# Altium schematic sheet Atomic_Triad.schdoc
size 594 x 419 mm; Symbol: Drawing-Symbol_A4; @Project Name: Inverted_MAML_6x6; @Page Count: 1; @Update Date: 2026-06-10; @Create Date: 2026-06-10; @Schematic Name: Schematic1; @Page No: 1; @Page Name: P1; Company: EasyEDA.com; Version: V1.0; Page Size: A4; Drawn: Olle Welin; Device: Drawing-Symbol_A4; @Create Time: 18:31:32; @Update Time: 18:31:32; Border: 1; Width: 2338; Height: 1652; Region Start: 1; X Region Count: 6; Y Region Count: 4; Blade Width: 10; Title Block Position: 3; @Board Name: Analog_Matrix
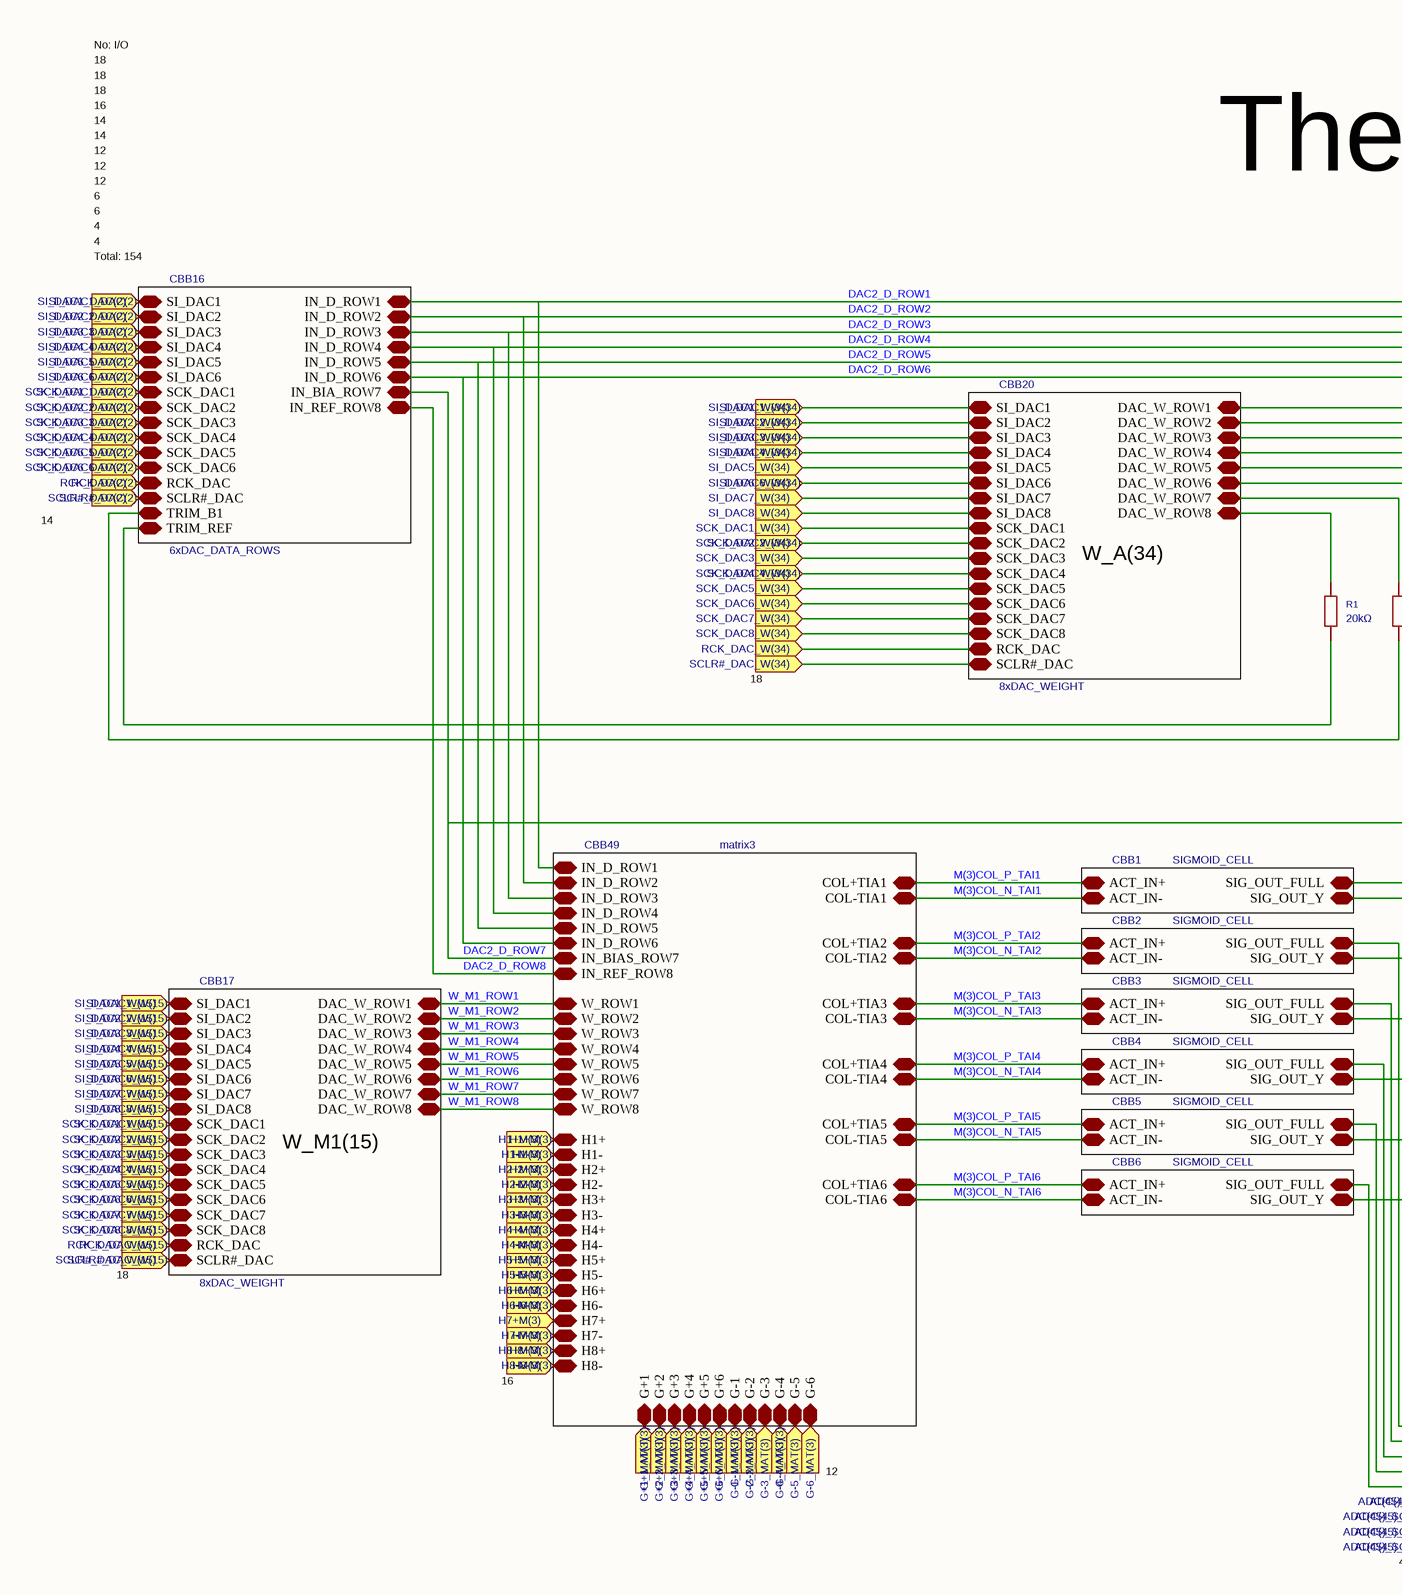
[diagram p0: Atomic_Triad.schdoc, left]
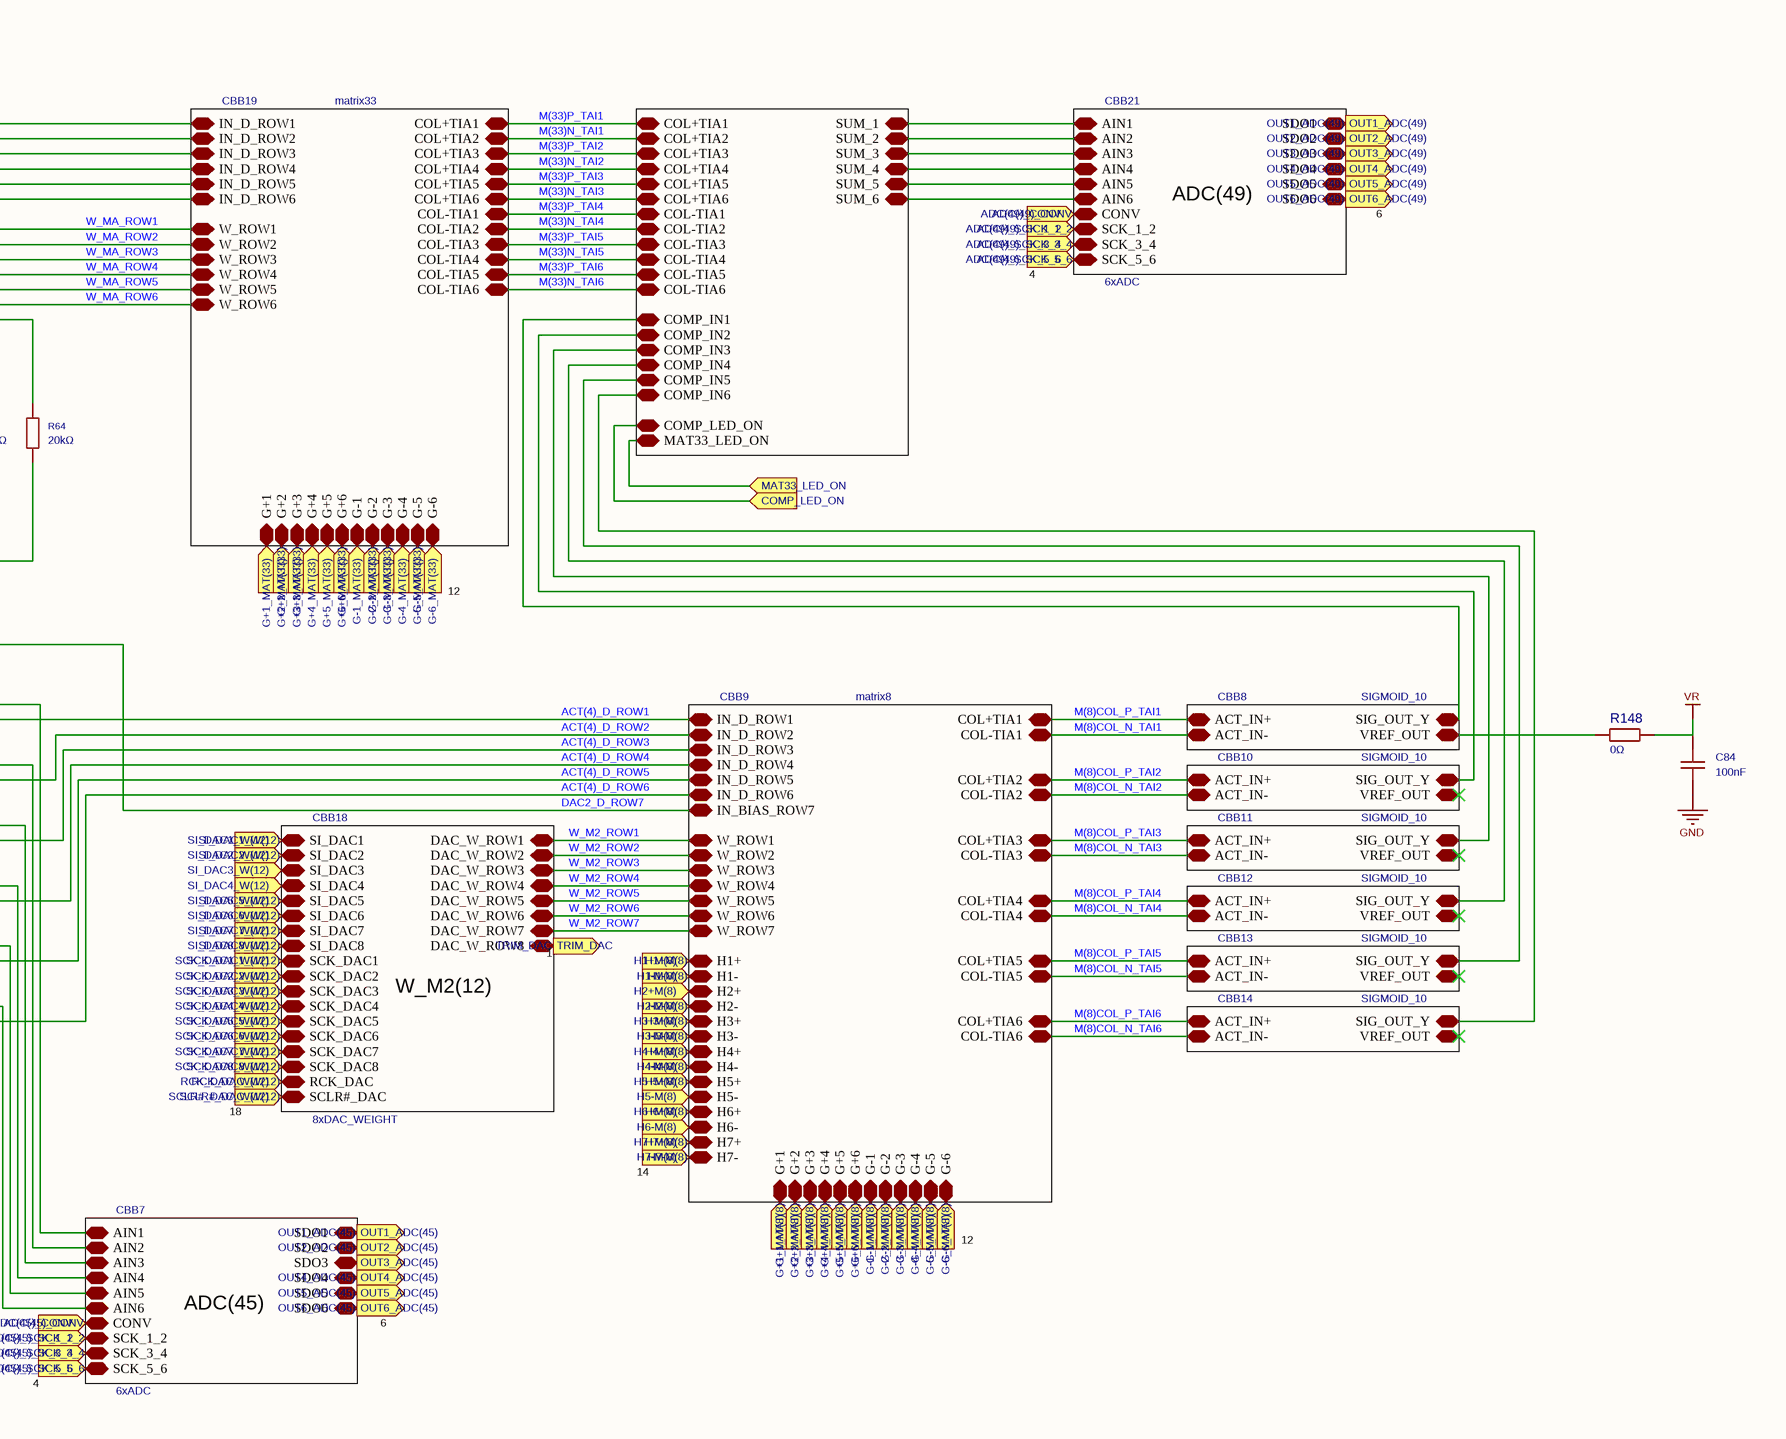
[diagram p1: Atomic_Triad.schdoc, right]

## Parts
C84  100nF  [C0402]
R1  20kΩ  [R0402]
R64  20kΩ  [R0402]
R148  0Ω  [R0402]

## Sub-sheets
CBB1 = SIMOID(4).schdoc: ACT_IN-, ACT_IN+, SIG_OUT_FULL, SIG_OUT_Y  | Symbol: SIGMOID_CELL
CBB2 = SIMOID(4).schdoc: ACT_IN-, ACT_IN+, SIG_OUT_FULL, SIG_OUT_Y  | Symbol: SIGMOID_CELL
CBB3 = SIMOID(4).schdoc: ACT_IN-, ACT_IN+, SIG_OUT_FULL, SIG_OUT_Y  | Symbol: SIGMOID_CELL
CBB4 = SIMOID(4).schdoc: ACT_IN-, ACT_IN+, SIG_OUT_FULL, SIG_OUT_Y  | Symbol: SIGMOID_CELL
CBB5 = SIMOID(4).schdoc: ACT_IN-, ACT_IN+, SIG_OUT_FULL, SIG_OUT_Y  | Symbol: SIGMOID_CELL
CBB6 = SIMOID(4).schdoc: ACT_IN-, ACT_IN+, SIG_OUT_FULL, SIG_OUT_Y  | Symbol: SIGMOID_CELL
CBB7 = ADC_BANK.schdoc: AIN1, CONV, SCK_1_2, SDO1, SDO2, SDO3, SDO4, SDO5, SDO6, AIN2, AIN3, AIN4, AIN5, AIN6, SCK_3_4, SCK_5_6  | Symbol: 6xADC
CBB8 = SIGMOID(10).schdoc: ACT_IN-, ACT_IN+, SIG_OUT_Y, VREF_OUT  | Symbol: SIGMOID_10
CBB9 = matx8.schdoc: H7+, H7-, H6-, H5-, H4-, H3-, H2-, H1-, H6+, H5+, H4+, H3+, H2+, H1+, COL-TIA6, COL-TIA5, COL-TIA4, COL-TIA3, COL-TIA2, COL-TIA1, COL+TIA6, COL+TIA5, COL+TIA4, COL+TIA3, COL+TIA2, COL+TIA1, G-6, G-5, G-4, G-3, G-2, G-1, G+6, G+5, G+4, G+3, G+2, G+1, IN_D_ROW1, IN_D_ROW2, IN_D_ROW3, IN_D_ROW4, IN_D_ROW5, IN_D_ROW6, W_ROW1, W_ROW2, W_ROW3, W_ROW4, W_ROW5, W_ROW6, W_ROW7, IN_BIAS_ROW7  | Symbol: matrix8
CBB10 = SIGMOID(10).schdoc: ACT_IN-, ACT_IN+, SIG_OUT_Y, VREF_OUT  | Symbol: SIGMOID_10
CBB11 = SIGMOID(10).schdoc: ACT_IN-, ACT_IN+, SIG_OUT_Y, VREF_OUT  | Symbol: SIGMOID_10
CBB12 = SIGMOID(10).schdoc: ACT_IN-, ACT_IN+, SIG_OUT_Y, VREF_OUT  | Symbol: SIGMOID_10
CBB13 = SIGMOID(10).schdoc: ACT_IN-, ACT_IN+, SIG_OUT_Y, VREF_OUT  | Symbol: SIGMOID_10
CBB14 = SIGMOID(10).schdoc: ACT_IN-, ACT_IN+, SIG_OUT_Y, VREF_OUT  | Symbol: SIGMOID_10
CBB15 = sum35.schdoc: COL+TIA1, COL+TIA2, COL+TIA3, COL+TIA4, COL+TIA5, COL+TIA6, COL-TIA1, COL-TIA2, COL-TIA3, COL-TIA4, COL-TIA5, COL-TIA6, COMP_IN1, COMP_IN2, COMP_IN3, COMP_IN4, COMP_IN5, COMP_IN6, SUM_1, SUM_2, SUM_3, SUM_4, SUM_5, SUM_6, COMP_LED_ON, MAT33_LED_ON  | Symbol: SUM35
CBB16 = 6xDAC_8-bit.schdoc: SI_DAC1, SI_DAC2, SI_DAC3, SI_DAC4, SI_DAC5, SI_DAC6, SCK_DAC1, SCK_DAC2, SCK_DAC3, SCK_DAC4, SCK_DAC5, SCK_DAC6, RCK_DAC, SCLR#_DAC, IN_BIA_ROW7, IN_REF_ROW8, IN_D_ROW1, IN_D_ROW2, IN_D_ROW3, IN_D_ROW4, IN_D_ROW5, IN_D_ROW6, TRIM_B1, TRIM_REF  | Symbol: 6xDAC_DATA_ROWS
CBB17 = 8xDAC_WEIGHT_8xDAC_8-bit.schdoc: SI_DAC1, SI_DAC2, SI_DAC3, SI_DAC4, SI_DAC5, SI_DAC6, SI_DAC7, SI_DAC8, SCK_DAC1, SCK_DAC2, SCK_DAC3, SCK_DAC4, SCK_DAC5, SCK_DAC6, SCK_DAC7, SCK_DAC8, RCK_DAC, SCLR#_DAC, DAC_W_ROW1, DAC_W_ROW2, DAC_W_ROW3, DAC_W_ROW4, DAC_W_ROW5, DAC_W_ROW6, DAC_W_ROW7, DAC_W_ROW8  | Symbol: 8xDAC_WEIGHT
CBB18 = 8xDAC_WEIGHT_8xDAC_8-bit.schdoc: SI_DAC1, SI_DAC2, SI_DAC3, SI_DAC4, SI_DAC5, SI_DAC6, SI_DAC7, SI_DAC8, SCK_DAC1, SCK_DAC2, SCK_DAC3, SCK_DAC4, SCK_DAC5, SCK_DAC6, SCK_DAC7, SCK_DAC8, RCK_DAC, SCLR#_DAC, DAC_W_ROW1, DAC_W_ROW2, DAC_W_ROW3, DAC_W_ROW4, DAC_W_ROW5, DAC_W_ROW6, DAC_W_ROW7, DAC_W_ROW8  | Symbol: 8xDAC_WEIGHT
CBB19 = matx33.schdoc: G+1, G+2, G+3, G+4, G+5, G+6, G-1, G-2, G-3, G-4, G-5, G-6, IN_D_ROW1, IN_D_ROW2, IN_D_ROW3, IN_D_ROW4, IN_D_ROW5, IN_D_ROW6, W_ROW1, W_ROW2, W_ROW3, W_ROW4, W_ROW5, W_ROW6, COL+TIA1, COL+TIA2, COL+TIA3, COL+TIA4, COL+TIA5, COL+TIA6, COL-TIA1, COL-TIA2, COL-TIA3, COL-TIA4, COL-TIA5, COL-TIA6  | Symbol: matrix33
CBB20 = 8xDAC_WEIGHT_8xDAC_8-bit.schdoc: SI_DAC1, SI_DAC2, SI_DAC3, SI_DAC4, SI_DAC5, SI_DAC6, SI_DAC7, SI_DAC8, SCK_DAC1, SCK_DAC2, SCK_DAC3, SCK_DAC4, SCK_DAC5, SCK_DAC6, SCK_DAC7, SCK_DAC8, RCK_DAC, SCLR#_DAC, DAC_W_ROW1, DAC_W_ROW2, DAC_W_ROW3, DAC_W_ROW4, DAC_W_ROW5, DAC_W_ROW6, DAC_W_ROW7, DAC_W_ROW8  | Symbol: 8xDAC_WEIGHT
CBB21 = ADC_BANK.schdoc: AIN1, CONV, SCK_1_2, SDO1, SDO2, SDO3, SDO4, SDO5, SDO6, AIN2, AIN3, AIN4, AIN5, AIN6, SCK_3_4, SCK_5_6  | Symbol: 6xADC
CBB49 = matx3.schdoc: G+1, G+2, G+3, G+4, G+5, G+6, G-1, G-2, G-3, G-4, G-5, G-6, COL+TIA1, COL+TIA2, COL+TIA3, COL+TIA4, COL+TIA5, COL+TIA6, COL-TIA1, COL-TIA2, COL-TIA3, COL-TIA4, COL-TIA5, COL-TIA6, H1+, H2+, H3+, H4+, H5+, H6+, H1-, H2-, H3-, H4-, H5-, H6-, H7-, H8-, H7+, H8+, W_ROW1, W_ROW2, W_ROW3, W_ROW4, W_ROW5, W_ROW6, W_ROW7, W_ROW8, IN_D_ROW1, IN_D_ROW2, IN_D_ROW3, IN_D_ROW4, IN_D_ROW5, IN_D_ROW6, IN_BIAS_ROW7, IN_REF_ROW8  | Symbol: matrix3

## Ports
ADC(45)_CONV (in), ADC(45)_SCK_1_2 (in), ADC(45)_SCK_3_4 (in), ADC(45)_SCK_5_6 (in), ADC(49)_CONV (in), ADC(49)_SCK_1_2 (in), ADC(49)_SCK_3_4 (in), ADC(49)_SCK_5_6 (in), COMP_LED_ON (in), G+1_MAT(3) (in), G+1_MAT(8) (in), G+1_MAT(33) (in), G+2_MAT(3) (in), G+2_MAT(8) (in), G+2_MAT(33) (in), G+3_MAT(3) (in), G+3_MAT(8) (in), G+3_MAT(33) (in), G+4_MAT(3) (in), G+4_MAT(8) (in), G+4_MAT(33) (in), G+5_MAT(3) (in), G+5_MAT(8) (in), G+5_MAT(33) (in), G+6_MAT(3) (in), G+6_MAT(8) (in), G+6_MAT(33) (in), G-1_MAT(3) (in), G-1_MAT(8) (in), G-1_MAT(33) (in), G-2_MAT(3) (in), G-2_MAT(8) (in), G-2_MAT(33) (in), G-3_MAT(3) (in), G-3_MAT(8) (in), G-3_MAT(33) (in), G-4_MAT(3) (in), G-4_MAT(8) (in), G-4_MAT(33) (in), G-5_MAT(3) (in), G-5_MAT(8) (in), G-5_MAT(33) (in), G-6_MAT(3) (in), G-6_MAT(8) (in), G-6_MAT(33) (in), H1+M(3) (in), H1+M(8) (in), H1-M(3) (in), H1-M(8) (in), H2+M(3) (in), H2+M(8) (in), H2-M(3) (in), H2-M(8) (in), H3+M(3) (in), H3+M(8) (in), H3-M(3) (in), H3-M(8) (in), H4+M(3) (in), H4+M(8) (in), H4-M(3) (in), H4-M(8) (in), H5+M(3) (in), H5+M(8) (in), H5-M(3) (in), H5-M(8) (in), H6+M(3) (in), H6+M(8) (in), H6-M(3) (in), H6-M(8) (in), H7+M(3) (in), H7+M(8) (in), H7-M(3) (in), H7-M(8) (in), H8+M(3) (in), H8-M(3) (in), MAT33_LED_ON (in), OUT1_ADC(45) (out), OUT1_ADC(49) (out), OUT2_ADC(45) (out), OUT2_ADC(49) (out), OUT3_ADC(45) (out), OUT3_ADC(49) (out), OUT4_ADC(45) (out), OUT4_ADC(49) (out), OUT5_ADC(45) (out), OUT5_ADC(49) (out), OUT6_ADC(45) (out), OUT6_ADC(49) (out), RCK_DAC(2) (in), RCK_DAC_W(12) (in), RCK_DAC_W(15) (in), RCK_DAC_W(34) (in), SCK_DAC1_DAC(2) (in), SCK_DAC1_W(12) (in), SCK_DAC1_W(15) (in), SCK_DAC1_W(34) (in), SCK_DAC2_DAC(2) (in), SCK_DAC2_W(12) (in), SCK_DAC2_W(15) (in), SCK_DAC2_W(34) (in), SCK_DAC3_DAC(2) (in), SCK_DAC3_W(12) (in), SCK_DAC3_W(15) (in), SCK_DAC3_W(34) (in), SCK_DAC4_DAC(2) (in), SCK_DAC4_W(12) (in), SCK_DAC4_W(15) (in), SCK_DAC4_W(34) (in), SCK_DAC5_DAC(2) (in), SCK_DAC5_W(12) (in), SCK_DAC5_W(15) (in), SCK_DAC5_W(34) (in), SCK_DAC6_DAC(2) (in), SCK_DAC6_W(12) (in), SCK_DAC6_W(15) (in), SCK_DAC6_W(34) (in), SCK_DAC7_W(12) (in), SCK_DAC7_W(15) (in), SCK_DAC7_W(34) (in), SCK_DAC8_W(12) (in), SCK_DAC8_W(15) (in), SCK_DAC8_W(34) (in), SCLR#_DAC(2) (in), SCLR#_DAC_W(12) (in), SCLR#_DAC_W(15) (in), SCLR#_DAC_W(34) (in), SI_DAC1_DAC(2) (in), SI_DAC1_W(12) (in), SI_DAC1_W(15) (in), SI_DAC1_W(34) (in), SI_DAC2_DAC(2) (in), SI_DAC2_W(12) (in), SI_DAC2_W(15) (in), SI_DAC2_W(34) (in), SI_DAC3_DAC(2) (in), SI_DAC3_W(12) (in), SI_DAC3_W(15) (in), SI_DAC3_W(34) (in), SI_DAC4_DAC(2) (in), SI_DAC4_W(12) (in), SI_DAC4_W(15) (in), SI_DAC4_W(34) (in), SI_DAC5_DAC(2) (in), SI_DAC5_W(12) (in), SI_DAC5_W(15) (in), SI_DAC5_W(34) (in), SI_DAC6_DAC(2) (in), SI_DAC6_W(12) (in), SI_DAC6_W(15) (in), SI_DAC6_W(34) (in), SI_DAC7_W(12) (in), SI_DAC7_W(15) (in), SI_DAC7_W(34) (in), SI_DAC8_W(12) (in), SI_DAC8_W(15) (in), SI_DAC8_W(34) (in), TRIM_DAC (out)

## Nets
GND: C84.1
VR: C84.2 R148.2
ACT(4)_D_ROW1: sheet CBB1/SIG_OUT_Y, sheet CBB9/IN_D_ROW1
ACT(4)_D_ROW2: sheet CBB2/SIG_OUT_Y, sheet CBB9/IN_D_ROW2
ACT(4)_D_ROW3: sheet CBB3/SIG_OUT_Y, sheet CBB9/IN_D_ROW3
ACT(4)_D_ROW4: sheet CBB4/SIG_OUT_Y, sheet CBB9/IN_D_ROW4
ACT(4)_D_ROW5: sheet CBB5/SIG_OUT_Y, sheet CBB9/IN_D_ROW5
ACT(4)_D_ROW6: sheet CBB6/SIG_OUT_Y, sheet CBB9/IN_D_ROW6
ADC(45)_CONV: port ADC(45)_CONV, sheet CBB7/CONV
ADC(45)_SCK_1_2: port ADC(45)_SCK_1_2, sheet CBB7/SCK_1_2
ADC(45)_SCK_3_4: port ADC(45)_SCK_3_4, sheet CBB7/SCK_3_4
ADC(45)_SCK_5_6: port ADC(45)_SCK_5_6, sheet CBB7/SCK_5_6
ADC(49)_CONV: port ADC(49)_CONV, sheet CBB21/CONV
ADC(49)_SCK_1_2: port ADC(49)_SCK_1_2, sheet CBB21/SCK_1_2
ADC(49)_SCK_3_4: port ADC(49)_SCK_3_4, sheet CBB21/SCK_3_4
ADC(49)_SCK_5_6: port ADC(49)_SCK_5_6, sheet CBB21/SCK_5_6
COMP_LED_ON: port COMP_LED_ON, sheet CBB15/COMP_LED_ON
DAC2_D_ROW1: sheet CBB49/IN_D_ROW1, sheet CBB16/IN_D_ROW1, sheet CBB19/IN_D_ROW1
DAC2_D_ROW2: sheet CBB49/IN_D_ROW2, sheet CBB16/IN_D_ROW2, sheet CBB19/IN_D_ROW2
DAC2_D_ROW3: sheet CBB49/IN_D_ROW3, sheet CBB16/IN_D_ROW3, sheet CBB19/IN_D_ROW3
DAC2_D_ROW4: sheet CBB49/IN_D_ROW4, sheet CBB16/IN_D_ROW4, sheet CBB19/IN_D_ROW4
DAC2_D_ROW5: sheet CBB49/IN_D_ROW5, sheet CBB16/IN_D_ROW5, sheet CBB19/IN_D_ROW5
DAC2_D_ROW6: sheet CBB49/IN_D_ROW6, sheet CBB16/IN_D_ROW6, sheet CBB19/IN_D_ROW6
DAC2_D_ROW7: sheet CBB49/IN_BIAS_ROW7, sheet CBB9/IN_BIAS_ROW7, sheet CBB16/IN_BIA_ROW7
DAC2_D_ROW8: sheet CBB49/IN_REF_ROW8, sheet CBB16/IN_REF_ROW8
G+1_MAT(3): port G+1_MAT(3), sheet CBB49/G+1
G+1_MAT(8): port G+1_MAT(8), sheet CBB9/G+1
G+1_MAT(33): port G+1_MAT(33), sheet CBB19/G+1
G+2_MAT(3): port G+2_MAT(3), sheet CBB49/G+2
G+2_MAT(8): port G+2_MAT(8), sheet CBB9/G+2
G+2_MAT(33): port G+2_MAT(33), sheet CBB19/G+2
G+3_MAT(3): port G+3_MAT(3), sheet CBB49/G+3
G+3_MAT(8): port G+3_MAT(8), sheet CBB9/G+3
G+3_MAT(33): port G+3_MAT(33), sheet CBB19/G+3
G+4_MAT(3): port G+4_MAT(3), sheet CBB49/G+4
G+4_MAT(8): port G+4_MAT(8), sheet CBB9/G+4
G+4_MAT(33): port G+4_MAT(33), sheet CBB19/G+4
G+5_MAT(3): port G+5_MAT(3), sheet CBB49/G+5
G+5_MAT(8): port G+5_MAT(8), sheet CBB9/G+5
G+5_MAT(33): port G+5_MAT(33), sheet CBB19/G+5
G+6_MAT(3): port G+6_MAT(3), sheet CBB49/G+6
G+6_MAT(8): port G+6_MAT(8), sheet CBB9/G+6
G+6_MAT(33): port G+6_MAT(33), sheet CBB19/G+6
G-1_MAT(3): port G-1_MAT(3), sheet CBB49/G-1
G-1_MAT(8): port G-1_MAT(8), sheet CBB9/G-1
G-1_MAT(33): port G-1_MAT(33), sheet CBB19/G-1
G-2_MAT(3): port G-2_MAT(3), sheet CBB49/G-2
G-2_MAT(8): port G-2_MAT(8), sheet CBB9/G-2
G-2_MAT(33): port G-2_MAT(33), sheet CBB19/G-2
G-3_MAT(3): port G-3_MAT(3), sheet CBB49/G-3
G-3_MAT(8): port G-3_MAT(8), sheet CBB9/G-3
G-3_MAT(33): port G-3_MAT(33), sheet CBB19/G-3
G-4_MAT(3): port G-4_MAT(3), sheet CBB49/G-4
G-4_MAT(8): port G-4_MAT(8), sheet CBB9/G-4
G-4_MAT(33): port G-4_MAT(33), sheet CBB19/G-4
G-5_MAT(3): port G-5_MAT(3), sheet CBB49/G-5
G-5_MAT(8): port G-5_MAT(8), sheet CBB9/G-5
G-5_MAT(33): port G-5_MAT(33), sheet CBB19/G-5
G-6_MAT(3): port G-6_MAT(3), sheet CBB49/G-6
G-6_MAT(8): port G-6_MAT(8), sheet CBB9/G-6
G-6_MAT(33): port G-6_MAT(33), sheet CBB19/G-6
H1+M(3): port H1+M(3), sheet CBB49/H1+
H1+M(8): port H1+M(8), sheet CBB9/H1+
H1-M(3): port H1-M(3), sheet CBB49/H1-
H1-M(8): port H1-M(8), sheet CBB9/H1-
H2+M(3): port H2+M(3), sheet CBB49/H2+
H2+M(8): port H2+M(8), sheet CBB9/H2+
H2-M(3): port H2-M(3), sheet CBB49/H2-
H2-M(8): port H2-M(8), sheet CBB9/H2-
H3+M(3): port H3+M(3), sheet CBB49/H3+
H3+M(8): port H3+M(8), sheet CBB9/H3+
H3-M(3): port H3-M(3), sheet CBB49/H3-
H3-M(8): port H3-M(8), sheet CBB9/H3-
H4+M(3): port H4+M(3), sheet CBB49/H4+
H4+M(8): port H4+M(8), sheet CBB9/H4+
H4-M(3): port H4-M(3), sheet CBB49/H4-
H4-M(8): port H4-M(8), sheet CBB9/H4-
H5+M(3): port H5+M(3), sheet CBB49/H5+
H5+M(8): port H5+M(8), sheet CBB9/H5+
H5-M(3): port H5-M(3), sheet CBB49/H5-
H5-M(8): port H5-M(8), sheet CBB9/H5-
H6+M(3): port H6+M(3), sheet CBB49/H6+
H6+M(8): port H6+M(8), sheet CBB9/H6+
H6-M(3): port H6-M(3), sheet CBB49/H6-
H6-M(8): port H6-M(8), sheet CBB9/H6-
H7+M(3): port H7+M(3), sheet CBB49/H7+
H7+M(8): port H7+M(8), sheet CBB9/H7+
H7-M(3): port H7-M(3), sheet CBB49/H7-
H7-M(8): port H7-M(8), sheet CBB9/H7-
H8+M(3): port H8+M(3), sheet CBB49/H8+
H8-M(3): port H8-M(3), sheet CBB49/H8-
M(3)COL_N_TAI1: sheet CBB49/COL-TIA1, sheet CBB1/ACT_IN-
M(3)COL_N_TAI2: sheet CBB49/COL-TIA2, sheet CBB2/ACT_IN-
M(3)COL_N_TAI3: sheet CBB49/COL-TIA3, sheet CBB3/ACT_IN-
M(3)COL_N_TAI4: sheet CBB49/COL-TIA4, sheet CBB4/ACT_IN-
M(3)COL_N_TAI5: sheet CBB49/COL-TIA5, sheet CBB5/ACT_IN-
M(3)COL_N_TAI6: sheet CBB49/COL-TIA6, sheet CBB6/ACT_IN-
M(3)COL_P_TAI1: sheet CBB49/COL+TIA1, sheet CBB1/ACT_IN+
M(3)COL_P_TAI2: sheet CBB49/COL+TIA2, sheet CBB2/ACT_IN+
M(3)COL_P_TAI3: sheet CBB49/COL+TIA3, sheet CBB3/ACT_IN+
M(3)COL_P_TAI4: sheet CBB49/COL+TIA4, sheet CBB4/ACT_IN+
M(3)COL_P_TAI5: sheet CBB49/COL+TIA5, sheet CBB5/ACT_IN+
M(3)COL_P_TAI6: sheet CBB49/COL+TIA6, sheet CBB6/ACT_IN+
M(8)COL_N_TAI1: sheet CBB9/COL-TIA1, sheet CBB8/ACT_IN-
M(8)COL_N_TAI2: sheet CBB9/COL-TIA2, sheet CBB10/ACT_IN-
M(8)COL_N_TAI3: sheet CBB9/COL-TIA3, sheet CBB11/ACT_IN-
M(8)COL_N_TAI4: sheet CBB9/COL-TIA4, sheet CBB12/ACT_IN-
M(8)COL_N_TAI5: sheet CBB9/COL-TIA5, sheet CBB13/ACT_IN-
M(8)COL_N_TAI6: sheet CBB9/COL-TIA6, sheet CBB14/ACT_IN-
M(8)COL_P_TAI1: sheet CBB9/COL+TIA1, sheet CBB8/ACT_IN+
M(8)COL_P_TAI2: sheet CBB9/COL+TIA2, sheet CBB10/ACT_IN+
M(8)COL_P_TAI3: sheet CBB9/COL+TIA3, sheet CBB11/ACT_IN+
M(8)COL_P_TAI4: sheet CBB9/COL+TIA4, sheet CBB12/ACT_IN+
M(8)COL_P_TAI5: sheet CBB9/COL+TIA5, sheet CBB13/ACT_IN+
M(8)COL_P_TAI6: sheet CBB9/COL+TIA6, sheet CBB14/ACT_IN+
M(33)N_TAI1: sheet CBB19/COL+TIA2, sheet CBB15/COL+TIA2
M(33)N_TAI2: sheet CBB19/COL+TIA4, sheet CBB15/COL+TIA4
M(33)N_TAI3: sheet CBB19/COL+TIA6, sheet CBB15/COL+TIA6
M(33)N_TAI4: sheet CBB19/COL-TIA2, sheet CBB15/COL-TIA2
M(33)N_TAI5: sheet CBB19/COL-TIA4, sheet CBB15/COL-TIA4
M(33)N_TAI6: sheet CBB19/COL-TIA6, sheet CBB15/COL-TIA6
M(33)P_TAI1: sheet CBB19/COL+TIA1, sheet CBB15/COL+TIA1
M(33)P_TAI2: sheet CBB19/COL+TIA3, sheet CBB15/COL+TIA3
M(33)P_TAI3: sheet CBB19/COL+TIA5, sheet CBB15/COL+TIA5
M(33)P_TAI4: sheet CBB19/COL-TIA1, sheet CBB15/COL-TIA1
M(33)P_TAI5: sheet CBB19/COL-TIA3, sheet CBB15/COL-TIA3
M(33)P_TAI6: sheet CBB19/COL-TIA5, sheet CBB15/COL-TIA5
MAT33_LED_ON: port MAT33_LED_ON, sheet CBB15/MAT33_LED_ON
OUT1_ADC(45): port OUT1_ADC(45), sheet CBB7/SDO1
OUT1_ADC(49): port OUT1_ADC(49), sheet CBB21/SDO1
OUT2_ADC(45): port OUT2_ADC(45), sheet CBB7/SDO2
OUT2_ADC(49): port OUT2_ADC(49), sheet CBB21/SDO2
OUT3_ADC(45): port OUT3_ADC(45), sheet CBB7/SDO3
OUT3_ADC(49): port OUT3_ADC(49), sheet CBB21/SDO3
OUT4_ADC(45): port OUT4_ADC(45), sheet CBB7/SDO4
OUT4_ADC(49): port OUT4_ADC(49), sheet CBB21/SDO4
OUT5_ADC(45): port OUT5_ADC(45), sheet CBB7/SDO5
OUT5_ADC(49): port OUT5_ADC(49), sheet CBB21/SDO5
OUT6_ADC(45): port OUT6_ADC(45), sheet CBB7/SDO6
OUT6_ADC(49): port OUT6_ADC(49), sheet CBB21/SDO6
RCK_DAC(2): port RCK_DAC(2), sheet CBB16/RCK_DAC
RCK_DAC_W(12): port RCK_DAC_W(12), sheet CBB18/RCK_DAC
RCK_DAC_W(15): port RCK_DAC_W(15), sheet CBB17/RCK_DAC
RCK_DAC_W(34): port RCK_DAC_W(34), sheet CBB20/RCK_DAC
SCK_DAC1_DAC(2): port SCK_DAC1_DAC(2), sheet CBB16/SCK_DAC1
SCK_DAC1_W(12): port SCK_DAC1_W(12), sheet CBB18/SCK_DAC1
SCK_DAC1_W(15): port SCK_DAC1_W(15), sheet CBB17/SCK_DAC1
SCK_DAC1_W(34): port SCK_DAC1_W(34), sheet CBB20/SCK_DAC1
SCK_DAC2_DAC(2): port SCK_DAC2_DAC(2), sheet CBB16/SCK_DAC2
SCK_DAC2_W(12): port SCK_DAC2_W(12), sheet CBB18/SCK_DAC2
SCK_DAC2_W(15): port SCK_DAC2_W(15), sheet CBB17/SCK_DAC2
SCK_DAC2_W(34): port SCK_DAC2_W(34), sheet CBB20/SCK_DAC2
SCK_DAC3_DAC(2): port SCK_DAC3_DAC(2), sheet CBB16/SCK_DAC3
SCK_DAC3_W(12): port SCK_DAC3_W(12), sheet CBB18/SCK_DAC3
SCK_DAC3_W(15): port SCK_DAC3_W(15), sheet CBB17/SCK_DAC3
SCK_DAC3_W(34): port SCK_DAC3_W(34), sheet CBB20/SCK_DAC3
SCK_DAC4_DAC(2): port SCK_DAC4_DAC(2), sheet CBB16/SCK_DAC4
SCK_DAC4_W(12): port SCK_DAC4_W(12), sheet CBB18/SCK_DAC4
SCK_DAC4_W(15): port SCK_DAC4_W(15), sheet CBB17/SCK_DAC4
SCK_DAC4_W(34): port SCK_DAC4_W(34), sheet CBB20/SCK_DAC4
SCK_DAC5_DAC(2): port SCK_DAC5_DAC(2), sheet CBB16/SCK_DAC5
SCK_DAC5_W(12): port SCK_DAC5_W(12), sheet CBB18/SCK_DAC5
SCK_DAC5_W(15): port SCK_DAC5_W(15), sheet CBB17/SCK_DAC5
SCK_DAC5_W(34): port SCK_DAC5_W(34), sheet CBB20/SCK_DAC5
SCK_DAC6_DAC(2): port SCK_DAC6_DAC(2), sheet CBB16/SCK_DAC6
SCK_DAC6_W(12): port SCK_DAC6_W(12), sheet CBB18/SCK_DAC6
SCK_DAC6_W(15): port SCK_DAC6_W(15), sheet CBB17/SCK_DAC6
SCK_DAC6_W(34): port SCK_DAC6_W(34), sheet CBB20/SCK_DAC6
SCK_DAC7_W(12): port SCK_DAC7_W(12), sheet CBB18/SCK_DAC7
SCK_DAC7_W(15): port SCK_DAC7_W(15), sheet CBB17/SCK_DAC7
SCK_DAC7_W(34): port SCK_DAC7_W(34), sheet CBB20/SCK_DAC7
SCK_DAC8_W(12): port SCK_DAC8_W(12), sheet CBB18/SCK_DAC8
SCK_DAC8_W(15): port SCK_DAC8_W(15), sheet CBB17/SCK_DAC8
SCK_DAC8_W(34): port SCK_DAC8_W(34), sheet CBB20/SCK_DAC8
SCLR#_DAC(2): port SCLR#_DAC(2), sheet CBB16/SCLR#_DAC
SCLR#_DAC_W(12): port SCLR#_DAC_W(12), sheet CBB18/SCLR#_DAC
SCLR#_DAC_W(15): port SCLR#_DAC_W(15), sheet CBB17/SCLR#_DAC
SCLR#_DAC_W(34): port SCLR#_DAC_W(34), sheet CBB20/SCLR#_DAC
SI_DAC1_DAC(2): port SI_DAC1_DAC(2), sheet CBB16/SI_DAC1
SI_DAC1_W(12): port SI_DAC1_W(12), sheet CBB18/SI_DAC1
SI_DAC1_W(15): port SI_DAC1_W(15), sheet CBB17/SI_DAC1
SI_DAC1_W(34): port SI_DAC1_W(34), sheet CBB20/SI_DAC1
SI_DAC2_DAC(2): port SI_DAC2_DAC(2), sheet CBB16/SI_DAC2
SI_DAC2_W(12): port SI_DAC2_W(12), sheet CBB18/SI_DAC2
SI_DAC2_W(15): port SI_DAC2_W(15), sheet CBB17/SI_DAC2
SI_DAC2_W(34): port SI_DAC2_W(34), sheet CBB20/SI_DAC2
SI_DAC3_DAC(2): port SI_DAC3_DAC(2), sheet CBB16/SI_DAC3
SI_DAC3_W(12): port SI_DAC3_W(12), sheet CBB18/SI_DAC3
SI_DAC3_W(15): port SI_DAC3_W(15), sheet CBB17/SI_DAC3
SI_DAC3_W(34): port SI_DAC3_W(34), sheet CBB20/SI_DAC3
SI_DAC4_DAC(2): port SI_DAC4_DAC(2), sheet CBB16/SI_DAC4
SI_DAC4_W(12): port SI_DAC4_W(12), sheet CBB18/SI_DAC4
SI_DAC4_W(15): port SI_DAC4_W(15), sheet CBB17/SI_DAC4
SI_DAC4_W(34): port SI_DAC4_W(34), sheet CBB20/SI_DAC4
SI_DAC5_DAC(2): port SI_DAC5_DAC(2), sheet CBB16/SI_DAC5
SI_DAC5_W(12): port SI_DAC5_W(12), sheet CBB18/SI_DAC5
SI_DAC5_W(15): port SI_DAC5_W(15), sheet CBB17/SI_DAC5
SI_DAC5_W(34): port SI_DAC5_W(34), sheet CBB20/SI_DAC5
SI_DAC6_DAC(2): port SI_DAC6_DAC(2), sheet CBB16/SI_DAC6
SI_DAC6_W(12): port SI_DAC6_W(12), sheet CBB18/SI_DAC6
SI_DAC6_W(15): port SI_DAC6_W(15), sheet CBB17/SI_DAC6
SI_DAC6_W(34): port SI_DAC6_W(34), sheet CBB20/SI_DAC6
SI_DAC7_W(12): port SI_DAC7_W(12), sheet CBB18/SI_DAC7
SI_DAC7_W(15): port SI_DAC7_W(15), sheet CBB17/SI_DAC7
SI_DAC7_W(34): port SI_DAC7_W(34), sheet CBB20/SI_DAC7
SI_DAC8_W(12): port SI_DAC8_W(12), sheet CBB18/SI_DAC8
SI_DAC8_W(15): port SI_DAC8_W(15), sheet CBB17/SI_DAC8
SI_DAC8_W(34): port SI_DAC8_W(34), sheet CBB20/SI_DAC8
TRIM_DAC: port TRIM_DAC, sheet CBB18/DAC_W_ROW8
W_M1_ROW1: sheet CBB49/W_ROW1, sheet CBB17/DAC_W_ROW1
W_M1_ROW2: sheet CBB49/W_ROW2, sheet CBB17/DAC_W_ROW2
W_M1_ROW3: sheet CBB49/W_ROW3, sheet CBB17/DAC_W_ROW3
W_M1_ROW4: sheet CBB49/W_ROW4, sheet CBB17/DAC_W_ROW4
W_M1_ROW5: sheet CBB49/W_ROW5, sheet CBB17/DAC_W_ROW5
W_M1_ROW6: sheet CBB49/W_ROW6, sheet CBB17/DAC_W_ROW6
W_M1_ROW7: sheet CBB49/W_ROW7, sheet CBB17/DAC_W_ROW7
W_M1_ROW8: sheet CBB49/W_ROW8, sheet CBB17/DAC_W_ROW8
W_M2_ROW1: sheet CBB9/W_ROW1, sheet CBB18/DAC_W_ROW1
W_M2_ROW2: sheet CBB9/W_ROW2, sheet CBB18/DAC_W_ROW2
W_M2_ROW3: sheet CBB9/W_ROW3, sheet CBB18/DAC_W_ROW3
W_M2_ROW4: sheet CBB9/W_ROW4, sheet CBB18/DAC_W_ROW4
W_M2_ROW5: sheet CBB9/W_ROW5, sheet CBB18/DAC_W_ROW5
W_M2_ROW6: sheet CBB9/W_ROW6, sheet CBB18/DAC_W_ROW6
W_M2_ROW7: sheet CBB9/W_ROW7, sheet CBB18/DAC_W_ROW7
W_MA_ROW1: sheet CBB19/W_ROW1, sheet CBB20/DAC_W_ROW1
W_MA_ROW2: sheet CBB19/W_ROW2, sheet CBB20/DAC_W_ROW2
W_MA_ROW3: sheet CBB19/W_ROW3, sheet CBB20/DAC_W_ROW3
W_MA_ROW4: sheet CBB19/W_ROW4, sheet CBB20/DAC_W_ROW4
W_MA_ROW5: sheet CBB19/W_ROW5, sheet CBB20/DAC_W_ROW5
W_MA_ROW6: sheet CBB19/W_ROW6, sheet CBB20/DAC_W_ROW6
NetR1_1: R1.1 ; sheet CBB20/DAC_W_ROW8
NetR1_2: R1.2 ; sheet CBB16/TRIM_REF
NetR64_1: R64.1 ; sheet CBB20/DAC_W_ROW7
NetR64_2: R64.2 ; sheet CBB16/TRIM_B1
NetR148_1: R148.1 ; sheet CBB8/VREF_OUT
(unnamed): sheet CBB1/SIG_OUT_FULL, sheet CBB7/AIN1
(unnamed): sheet CBB2/SIG_OUT_FULL, sheet CBB7/AIN2  [a separate net that carries the same name]
(unnamed): sheet CBB3/SIG_OUT_FULL, sheet CBB7/AIN3  [a separate net that carries the same name]
(unnamed): sheet CBB4/SIG_OUT_FULL, sheet CBB7/AIN4  [a separate net that carries the same name]
(unnamed): sheet CBB5/SIG_OUT_FULL, sheet CBB7/AIN5  [a separate net that carries the same name]
(unnamed): sheet CBB6/SIG_OUT_FULL, sheet CBB7/AIN6  [a separate net that carries the same name]
(unnamed): sheet CBB10/SIG_OUT_Y, sheet CBB15/COMP_IN2  [a separate net that carries the same name]
(unnamed): sheet CBB11/SIG_OUT_Y, sheet CBB15/COMP_IN3  [a separate net that carries the same name]
(unnamed): sheet CBB12/SIG_OUT_Y, sheet CBB15/COMP_IN4  [a separate net that carries the same name]
(unnamed): sheet CBB13/SIG_OUT_Y, sheet CBB15/COMP_IN5  [a separate net that carries the same name]
(unnamed): sheet CBB14/SIG_OUT_Y, sheet CBB15/COMP_IN6  [a separate net that carries the same name]
(unnamed): sheet CBB21/AIN1, sheet CBB15/SUM_1  [a separate net that carries the same name]
(unnamed): sheet CBB21/AIN2, sheet CBB15/SUM_2  [a separate net that carries the same name]
(unnamed): sheet CBB21/AIN3, sheet CBB15/SUM_3  [a separate net that carries the same name]
(unnamed): sheet CBB21/AIN4, sheet CBB15/SUM_4  [a separate net that carries the same name]
(unnamed): sheet CBB21/AIN5, sheet CBB15/SUM_5  [a separate net that carries the same name]
(unnamed): sheet CBB21/AIN6, sheet CBB15/SUM_6  [a separate net that carries the same name]
(unnamed): sheet CBB15/COMP_IN1, sheet CBB8/SIG_OUT_Y  [a separate net that carries the same name]

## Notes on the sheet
- 18
- No: I/O
- 14
- 16
- 12
- 6
- The "ATOMIC TRIAD"
- 4
- Total: 154
- ADC(49)
- W_A(34)
- W_M1(15)
- W_M2(12)
- 1
- ADC(45)

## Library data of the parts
C84 = CL05B104KO5NNNC: Capacitance:100nF Tolerance:±10% Tolerance:±10% Voltage Rating:16V Temperature Coefficient:X7R; Manufacturer: SAMSUNG(三星); 3D Model: b7d13df3e9464d7a99d0651d1a5b4d570819f05c4eef4c71ace90d822a990e87; 3D Model Transform: 39.37,19.685,0,0,0,0,0,0,0; Tolerance: ±10%; Voltage Rating: 16V; Temperature Coefficient: X7R; Add into BOM: no; ConvertToPcb: yes; ModelName: C0402_L1.0-W0.5-H0.5
R1 R64 = 0402WGF2002TCE: Type:Thick Film Resistors Resistance:20kΩ Tolerance:±1% Tolerance:±1% Power(Watts): Overload Voltage (Max): Temperature Coefficient:±100ppm/℃ Temperature Coefficient:±100ppm/℃ Operating Temperature Range:-55℃~+155℃ Operating Temperature Range:-55℃~+155℃; Manufacturer: UNI-ROYAL(厚声); 3D Model: efdecb7dae4442949d28eecaf748420f0819f05c4eef4c71ace90d822a990e87; 3D Model Transform: 39.37,19.685,0,0,0,0,0,0,0; Tolerance: ±1%; AddInBom: yes; ModelName: R0402_L1.0-W0.5-H0.4
R148 = 0402WGF0000TCE: Type:Thick Film Resistor Resistance:0Ω Tolerance:±1% Tolerance:±1% Power(Watts):62.5mW Voltage-Supply(Max):50V Temperature Coefficient:±800ppm/℃ Temperature Coefficient:±800ppm/℃ Operating Temperature:-55℃~+155℃ Operating Temperature:-55℃~+155℃; Manufacturer: UNI-ROYAL(厚声); 3D Model: efdecb7dae4442949d28eecaf748420f; 3D Model Transform: 39.37,19.685,0,0,0,0,0,0,0; Tolerance: ±1%; Power(Watts): 62.5mW; Voltage-Supply(Max): 50V; AddInBom: yes; ModelName: R0402_L1.0-W0.5-H0.4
